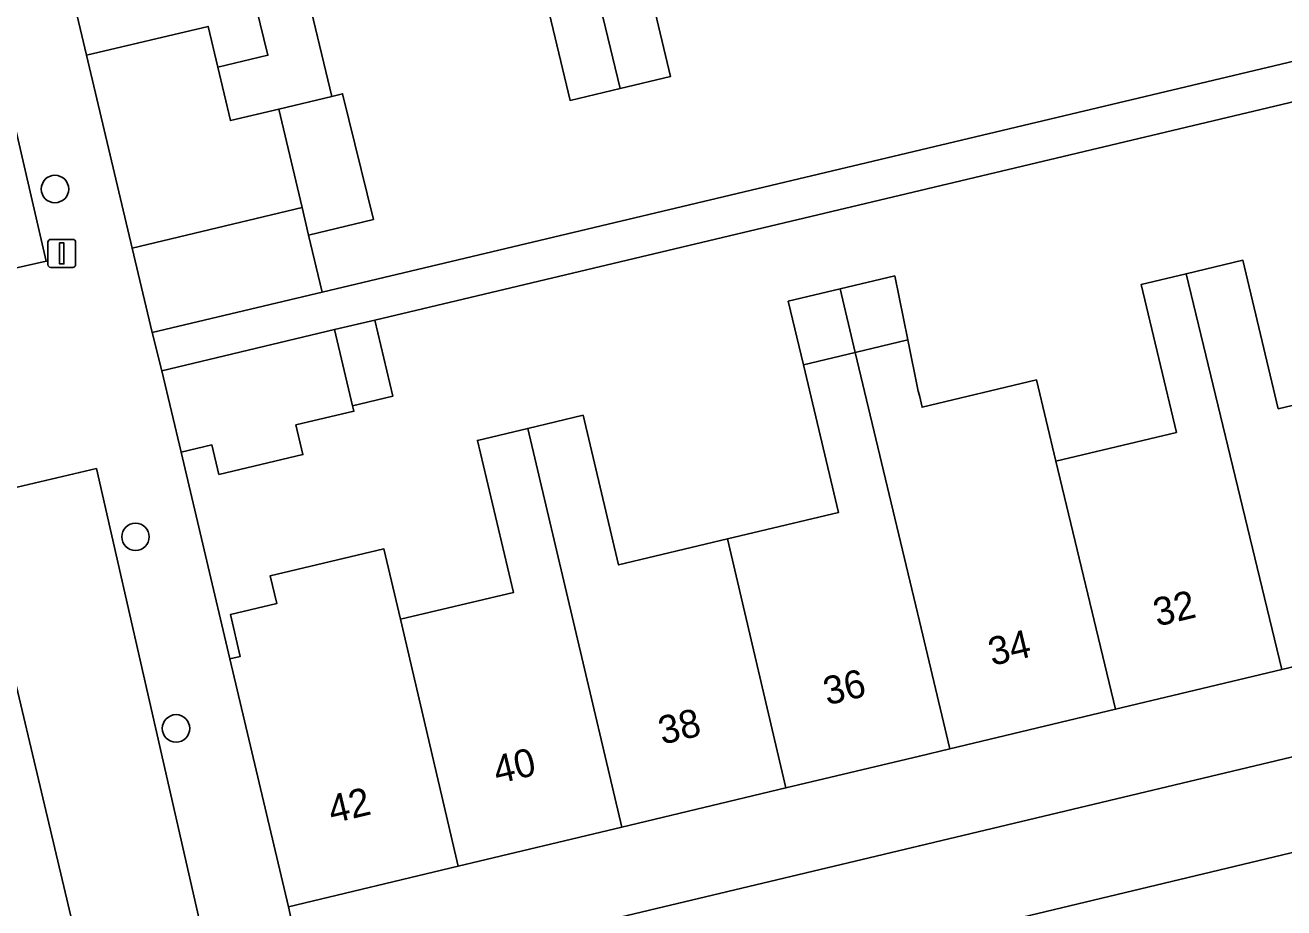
# Model space of a CAD drawing. Extents: x 158031 to 159244, y 380104 to 381214.
# Drawn here: x 158468.09 to 158513, y 380688.32 to 380719.79 of the extents above; entities that cross this region are included whole.
import ezdxf

# ---------------------------------------------------------------- set-up
doc = ezdxf.new("R2010")
doc.units = 0
for name, color, linetype in [('IMGEO_Boom', 7, 'Continuous'), ('IMGEO_Erf', 7, 'Continuous'), ('IMGEO_Lichtmast', 7, 'Continuous'), ('IMGEO_Pand', 7, 'Continuous'), ('IMGEO_Pand_nummerreeks', 7, 'Continuous'), ('IMGEO_Parkeervlak_open', 7, 'Continuous'), ('IMGEO_Rijbaan_lokaal_open', 7, 'Continuous'), ('IMGEO_Voetpad_open', 7, 'Continuous')]:
    doc.layers.add(name, color=color, linetype=linetype)

msp = doc.modelspace()

# ---------------------------------------------------------------- linework, layer by layer
at = {"layer": 'IMGEO_Boom'}
for centre in [(158469.155, 380713.953), (158472.027, 380701.549), (158473.474, 380694.72)]:
    msp.add_circle(centre, 0.489, dxfattribs=at)
at = {"layer": 'IMGEO_Erf'}
for points in [[(158489.843, 380723.317), (158491.115, 380717.964), (158489.328, 380717.54), (158487.534, 380717.114), (158486.26, 380722.476)], [(158478.242, 380720.571), (158479.03, 380717.254), (158479.42, 380717.347), (158480.516, 380712.867), (158478.207, 380712.303), (158478.688, 380710.278), (158519.715, 380720.024)], [(158521.442, 380718.991), (158480.571, 380709.28), (158481.215, 380706.567), (158479.776, 380706.226), (158479.823, 380706.03), (158477.753, 380705.538), (158478.003, 380704.485), (158475.005, 380703.773), (158474.755, 380704.826), (158473.657, 380704.565), (158475.389, 380697.195), (158475.769, 380697.285), (158475.415, 380698.776), (158477.067, 380699.169), (158476.832, 380700.157), (158480.895, 380701.122), (158481.482, 380698.611), (158485.518, 380699.57), (158484.23, 380704.991), (158486.028, 380705.418), (158487.999, 380705.886), (158489.266, 380700.551), (158493.154, 380701.475), (158497.113, 380702.415), (158495.861, 380707.687), (158495.323, 380709.952), (158497.172, 380710.392), (158499.123, 380710.856), (158499.589, 380708.573), (158499.962, 380706.747), (158500, 380706.588), (158500.099, 380706.172), (158504.177, 380707.143), (158504.873, 380704.251), (158509.172, 380705.274), (158507.915, 380710.551), (158509.518, 380710.933), (158511.545, 380711.415), (158512.806, 380706.119), (158516.593, 380707.021)], [(158545.592, 380705.924), (158541.989, 380705.066), (158538.398, 380704.211), (158538.719, 380702.862), (158536.487, 380702.331), (158534.187, 380701.783), (158533.864, 380703.14), (158531.404, 380702.555), (158530.342, 380702.302), (158530.184, 380702.264), (158530.484, 380701.008), (158524.618, 380699.608), (158518.779, 380698.214), (158512.93, 380696.819), (158507.003, 380695.404), (158501.086, 380693.992), (158500, 380693.733), (158495.238, 380692.596), (158489.379, 380691.198), (158483.54, 380689.804), (158477.488, 380688.36), (158478.148, 380685.33), (158500, 380690.536), (158567.068, 380706.513)]]:
    msp.add_lwpolyline(points, dxfattribs=at)
msp.add_lwpolyline([(158477.138, 380716.805), (158475.414, 380716.395), (158474.963, 380718.292), (158474.617, 380719.749), (158470.285, 380718.72), (158471.907, 380711.848), (158477.973, 380713.289)], close=True, dxfattribs=at)
at = {"layer": 'IMGEO_Lichtmast'}
for p, q in [((158469.002, 380712.156), (158469.792, 380712.156)), ((158469.792, 380712.156), (158469.002, 380712.156)), ((158468.902, 380711.256), (158468.902, 380712.056)), ((158468.902, 380712.056), (158468.902, 380711.256)), ((158469.892, 380712.056), (158469.892, 380711.256)), ((158469.892, 380711.256), (158469.892, 380712.056)), ((158469.792, 380711.156), (158469.002, 380711.156)), ((158469.002, 380711.156), (158469.792, 380711.156))]:
    msp.add_line(p, q, dxfattribs=at)
msp.add_lwpolyline([(158469.322, 380712.031), (158469.472, 380712.031), (158469.472, 380711.281), (158469.322, 380711.281), (158469.322, 380712.031)], dxfattribs=at)
for centre, start, end in [((158469.002, 380712.056), 90, 180), ((158469.002, 380712.056), 90, 180), ((158469.792, 380712.056), 0, 90), ((158469.792, 380712.056), 360, 90), ((158469.002, 380711.256), 180, 270), ((158469.002, 380711.256), 180, 270), ((158469.792, 380711.256), 270, 0), ((158469.792, 380711.256), 270, 0)]:
    msp.add_arc(centre, 0.1, start, end, dxfattribs=at)
at = {"layer": 'IMGEO_Pand'}
for points in [[(158489.328, 380717.54), (158491.115, 380717.964), (158489.843, 380723.317), (158493.877, 380724.275), (158491.747, 380733.041), (158485.912, 380731.656)], [(158489.328, 380717.54), (158485.912, 380731.656), (158480.094, 380730.274), (158482.248, 380721.523), (158486.26, 380722.476), (158487.534, 380717.114)], [(158480.094, 380730.274), (158474.268, 380728.891), (158476.756, 380718.72), (158474.963, 380718.292), (158475.414, 380716.395), (158477.138, 380716.805), (158479.03, 380717.254), (158478.242, 380720.571), (158482.248, 380721.523)], [(158474.268, 380728.891), (158468.21, 380727.452), (158470.285, 380718.72), (158474.617, 380719.749), (158474.963, 380718.292), (158476.756, 380718.72)], [(158479.03, 380717.254), (158477.138, 380716.805), (158477.973, 380713.289), (158478.207, 380712.303), (158480.516, 380712.867), (158479.42, 380717.347)], [(158478.207, 380712.303), (158477.973, 380713.289), (158471.907, 380711.848), (158472.622, 380708.837), (158478.688, 380710.278)], [(158516.593, 380707.021), (158512.806, 380706.119), (158511.545, 380711.415), (158509.518, 380710.933), (158512.93, 380696.819), (158518.779, 380698.214)], [(158497.172, 380710.392), (158497.712, 380708.127), (158499.589, 380708.573), (158499.123, 380710.856)], [(158509.518, 380710.933), (158507.915, 380710.551), (158509.172, 380705.274), (158504.873, 380704.251), (158507.003, 380695.404), (158512.93, 380696.819)], [(158497.172, 380710.392), (158495.323, 380709.952), (158495.861, 380707.687), (158497.712, 380708.127)], [(158479.132, 380708.938), (158472.966, 380707.473), (158473.657, 380704.565), (158474.755, 380704.826), (158475.005, 380703.773), (158478.003, 380704.485), (158477.753, 380705.538), (158479.823, 380706.03), (158479.776, 380706.226)], [(158480.571, 380709.28), (158479.132, 380708.938), (158479.776, 380706.226), (158481.215, 380706.567)], [(158504.873, 380704.251), (158504.177, 380707.143), (158500.099, 380706.172), (158500, 380706.588), (158499.962, 380706.747), (158499.589, 380708.573), (158497.712, 380708.127), (158500, 380698.541), (158501.086, 380693.992), (158507.003, 380695.404)], [(158495.238, 380692.596), (158500, 380693.733), (158501.086, 380693.992), (158500, 380698.541), (158497.712, 380708.127), (158495.861, 380707.687), (158497.113, 380702.415), (158493.154, 380701.475)], [(158495.238, 380692.596), (158493.154, 380701.475), (158489.266, 380700.551), (158487.999, 380705.886), (158486.028, 380705.418), (158489.379, 380691.198)], [(158489.379, 380691.198), (158486.028, 380705.418), (158484.23, 380704.991), (158485.518, 380699.57), (158481.482, 380698.611), (158483.54, 380689.804)], [(158481.482, 380698.611), (158480.895, 380701.122), (158476.832, 380700.157), (158477.067, 380699.169), (158475.415, 380698.776), (158475.769, 380697.285), (158475.389, 380697.195), (158477.488, 380688.36), (158483.54, 380689.804)]]:
    msp.add_lwpolyline(points, close=True, dxfattribs=at)
at = {"layer": 'IMGEO_Parkeervlak_open'}
for points in [[(158464.407, 380710.377), (158468.845, 380711.378), (158464.494, 380730.142), (158459.972, 380729.032)], [(158474.417, 380687.398), (158470.632, 380703.986), (158466.174, 380702.945), (158470.103, 380686.415)]]:
    msp.add_lwpolyline(points, close=True, dxfattribs=at)
msp.add_lwpolyline([(158568.163, 380703.411), (158500, 380687.103)], dxfattribs=at)
at = {"layer": 'IMGEO_Rijbaan_lokaal_open'}
msp.add_lwpolyline([(158465.25, 380776.353), (158458.389, 380774.771), (158448.498, 380772.49), (158443.849, 380771.419), (158448.9, 380750), (158465.02, 380682.236), (158470.774, 380683.592), (158470.103, 380686.415), (158466.174, 380702.945), (158464.407, 380710.377), (158459.972, 380729.032), (158458.956, 380733.307), (158474.565, 380737.039), (158471.494, 380750)], close=True, dxfattribs=at)
at = {"layer": 'IMGEO_Voetpad_open'}
msp.add_lwpolyline([(158515.725, 380742.86), (158514.435, 380742.553), (158514.382, 380742.54), (158515.307, 380738.636), (158516.459, 380733.771), (158517.376, 380729.899), (158519.715, 380720.024), (158478.688, 380710.278), (158472.622, 380708.837), (158472.966, 380707.473), (158479.132, 380708.938), (158480.571, 380709.28), (158521.442, 380718.991), (158521.04, 380720.689), (158564.728, 380731.038), (158564.379, 380732.511), (158556.459, 380730.636), (158552.37, 380729.668), (158526.203, 380723.472), (158520.628, 380722.152)], close=True, dxfattribs=at)
for points in [[(158468.008, 380731.157), (158468.101, 380731.266), (158468.203, 380731.366), (158468.313, 380731.457), (158468.431, 380731.537), (158468.556, 380731.607), (158468.687, 380731.665), (158464.494, 380730.142), (158468.845, 380711.378), (158464.407, 380710.377)], [(158466.174, 380702.945), (158470.632, 380703.986), (158474.417, 380687.398), (158475.055, 380684.601), (158478.148, 380685.33), (158477.488, 380688.36), (158475.389, 380697.195), (158473.657, 380704.565), (158472.966, 380707.473), (158472.622, 380708.837), (158471.907, 380711.848), (158470.285, 380718.72), (158468.21, 380727.452), (158467.702, 380729.868)], [(158620.444, 380718.631), (158615.556, 380718.152), (158573.761, 380708.16), (158570.352, 380707.295), (158567.068, 380706.513), (158500, 380690.536), (158478.148, 380685.33), (158475.055, 380684.601), (158470.774, 380683.592), (158465.02, 380682.236), (158462.621, 380681.705), (158458.268, 380680.768), (158452.408, 380679.382), (158444.752, 380677.453), (158441.902, 380676.775), (158437.459, 380675.717), (158427.098, 380673.251), (158417.251, 380670.908), (158417.108, 380670.868)], [(158500, 380687.103), (158568.163, 380703.411)]]:
    msp.add_lwpolyline(points, dxfattribs=at)

# ---------------------------------------------------------------- texts
at = {"layer": 'IMGEO_Pand_nummerreeks'}
for s, rotation, p in [('32', 13.4231, (158508.483, 380698.348)), ('34', 13.4244, (158502.598, 380696.944)), ('36', 13.4231, (158496.709, 380695.538)), ('38', 13.4231, (158490.824, 380694.134)), ('40', 13.4231, (158484.935, 380692.729)), ('42', 13.4244, (158479.041, 380691.321))]:
    msp.add_text(s, height=1, rotation=rotation, dxfattribs=at).set_placement(p)

doc.saveas('drawing.dxf')
